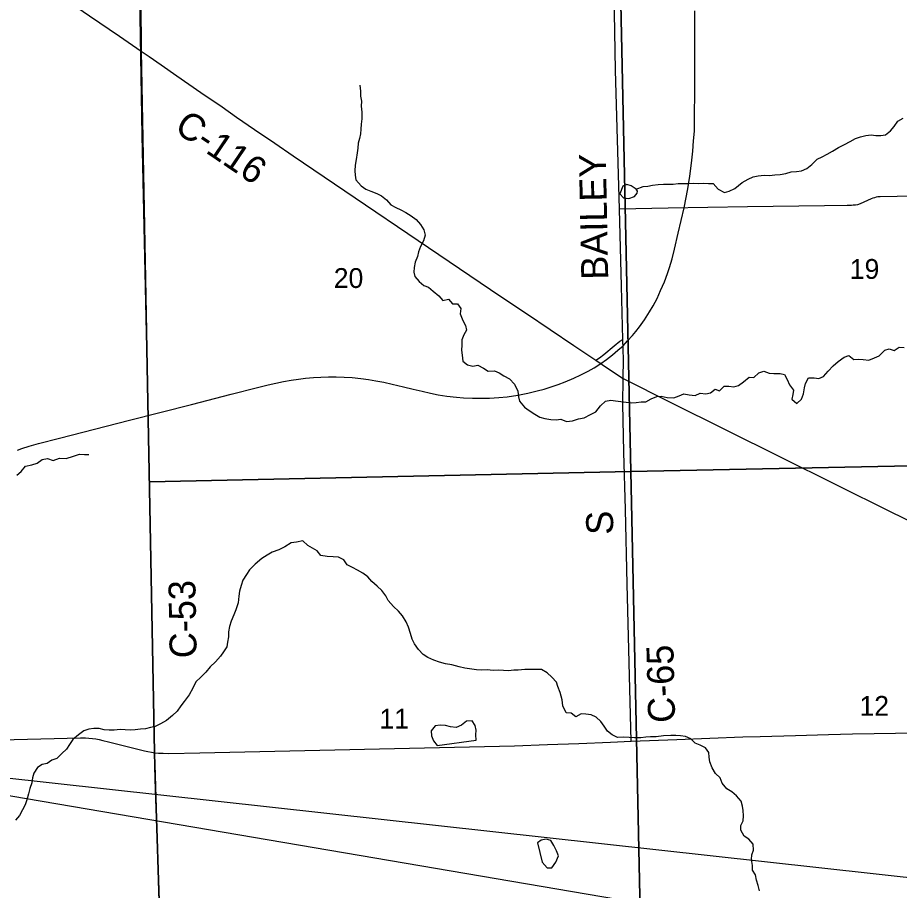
# Model space of a CAD drawing. Extents: x 0 to 34, y 0 to 22.
# Drawn here: x 6.483 to 8.341, y 13.008 to 14.847 of the extents above; entities that cross this region are included whole.
import ezdxf

# ---------------------------------------------------------------- set-up
doc = ezdxf.new("R2010")
doc.units = 0
for name, color, linetype in [('GM_X_Corporation', 7, 'Continuous'), ('GM_X_County_Road', 7, 'Continuous'), ('GM_X_County_Road_Text', 7, 'Continuous'), ('GM_X_Minor_Lake', 7, 'Continuous'), ('GM_X_Minor_River', 7, 'Continuous'), ('GM_X_Rail_Line', 7, 'Continuous'), ('GM_X_Section_Text', 7, 'Continuous'), ('GM_X_US_Route', 7, 'Continuous'), ('SH_Text', 7, 'Continuous')]:
    doc.layers.add(name, color=color, linetype=linetype)

msp = doc.modelspace()

# ---------------------------------------------------------------- linework, layer by layer
at = {"layer": 'GM_X_Corporation'}
for points in [[(9.5231, 10.8551), (9.5231, 15.9621), (9.2753, 15.9592), (8.467, 15.9428), (7.9287, 15.9357), (7.7194, 15.9329), (6.7217, 15.9197), (6.723, 15.8438), (6.7254, 15.7279), (6.7281, 15.6066), (6.7307, 15.471), (6.7334, 15.3315), (6.7355, 15.1761), (6.7389, 15.0216), (6.7431, 14.8113), (6.743, 14.7775), (6.7715, 13.2982), (6.7728, 13.2419), (6.7763, 13.1392), (6.7793, 13.0289), (6.7835, 12.8989)], [(6.7835, 12.8989), (6.7793, 13.0289), (6.7763, 13.1392), (6.7728, 13.2419), (6.7715, 13.2982), (6.743, 14.7775), (6.7431, 14.8113), (6.7389, 15.0216), (6.7355, 15.1761), (6.7334, 15.3315), (6.7307, 15.471), (6.7281, 15.6066), (6.7254, 15.7279), (6.723, 15.8438), (6.7217, 15.9197), (5.5749, 15.8972)]]:
    msp.add_lwpolyline(points, dxfattribs=at)
for points in [[(7.7535, 14.9111), (8.7607, 14.9294), (8.7817, 13.9109), (7.775, 13.8905)], [(6.74, 14.8913), (7.7535, 14.9111), (7.775, 13.8905), (6.7607, 13.8687), (6.7591, 13.9585), (6.7452, 14.5991)], [(8.7817, 13.9109), (8.8081, 12.8893), (7.797, 12.8624), (7.775, 13.8905)], [(7.775, 13.8905), (7.797, 12.8624), (6.7858, 12.8368), (6.7722, 13.2952), (6.7607, 13.8687)]]:
    msp.add_lwpolyline(points, close=True, dxfattribs=at)
at = {"layer": 'GM_X_County_Road'}
for points in [[(7.7586, 14.087), (7.7596, 14.1271), (7.7585, 14.1689), (7.7556, 14.2812), (7.7513, 14.4434), (7.7429, 14.7364), (7.7399, 14.8987), (7.7384, 14.9768), (7.7366, 15.1022), (7.7343, 15.2287), (7.732, 15.3689), (7.7302, 15.5067), (7.7285, 15.5987), (7.726, 15.729), (7.7231, 15.9143), (7.7228, 15.9196), (7.7225, 15.9234), (7.7219, 15.9266), (7.721, 15.9294), (7.7196, 15.9324), (7.7141, 15.942)], [(6.7432, 14.7769), (6.7433, 14.8108), (6.7391, 15.021), (6.7357, 15.1755), (6.7336, 15.331), (6.7309, 15.4704), (6.7283, 15.606), (6.7257, 15.7273), (6.7232, 15.8432), (6.7219, 15.9192)], [(5.583, 15.6276), (5.6406, 15.579), (5.6984, 15.53), (5.7316, 15.5018), (5.7952, 15.4488), (5.8729, 15.3853), (5.9476, 15.3251), (5.9861, 15.2948), (6.0143, 15.2742), (6.039, 15.257), (6.0726, 15.2344), (6.1308, 15.1946), (6.1902, 15.1544), (6.2678, 15.1015), (6.3063, 15.0753), (6.3366, 15.0543), (6.3799, 15.0246), (6.4366, 14.9859), (6.4904, 14.9497), (6.5207, 14.9291), (6.5698, 14.8958), (6.6343, 14.8515), (6.6973, 14.8086), (6.7432, 14.7769)], [(6.8063, 11.7845), (6.8015, 12.2917), (6.8011, 12.3125), (6.7964, 12.472), (6.7909, 12.6562), (6.7877, 12.7728), (6.7837, 12.8984), (6.7795, 13.0284), (6.7765, 13.1386), (6.773, 13.2414), (6.7717, 13.2976), (6.7432, 14.7769)], [(6.7432, 14.7769), (6.7599, 14.7656), (6.7855, 14.7476), (6.8182, 14.7248), (6.869, 14.6898), (6.9138, 14.6591), (6.9442, 14.6379), (6.982, 14.6119), (7.0246, 14.5827), (7.0631, 14.5562), (7.4572, 14.2892), (7.5013, 14.2598), (7.5553, 14.2236), (7.655, 14.1563), (7.7014, 14.1255), (7.7277, 14.1074), (7.7586, 14.087)], [(8.3758, 14.4713), (8.3366, 14.4705), (8.3003, 14.4699), (8.2959, 14.4695), (8.2918, 14.4687), (8.2884, 14.4678), (8.2847, 14.4665), (8.2816, 14.4651), (8.2584, 14.4548), (8.2525, 14.4529), (8.2484, 14.4522), (8.2437, 14.4519), (8.2399, 14.4516), (8.2358, 14.4516), (8.2312, 14.4516), (8.1834, 14.451), (8.0211, 14.4485), (7.8536, 14.4458), (7.7513, 14.4434)], [(7.7014, 14.1255), (7.7089, 14.1306), (7.718, 14.137), (7.7398, 14.1556), (7.752, 14.1654), (7.7585, 14.1689)], [(7.7757, 13.322), (7.7671, 13.653), (7.7639, 13.8108), (7.7602, 13.9313), (7.7582, 14.0333), (7.7586, 14.087)], [(7.7586, 14.087), (7.858, 14.037), (8.091, 13.921), (8.323, 13.8059), (8.4226, 13.7569), (8.6214, 13.6588), (8.8263, 13.5575), (8.9378, 13.5028), (9.0648, 13.4403), (9.1871, 13.3796)]]:
    msp.add_lwpolyline(points, dxfattribs=at)
at = {"layer": 'GM_X_Minor_Lake'}
for points in [[(7.7865, 14.4857), (7.7758, 14.4928), (7.7666, 14.4958), (7.7579, 14.4923), (7.752, 14.4763), (7.7593, 14.4672), (7.7707, 14.4662), (7.7825, 14.4705), (7.7885, 14.4777), (7.7888, 14.4815)], [(7.7888, 14.4815), (7.7865, 14.4857)], [(7.4491, 13.3245), (7.4486, 13.3355), (7.4489, 13.3454), (7.4473, 13.3552), (7.4408, 13.3654), (7.429, 13.3646), (7.4184, 13.3558), (7.4067, 13.3507), (7.3948, 13.3525), (7.3842, 13.3551), (7.3731, 13.3562), (7.3625, 13.3549), (7.3542, 13.3442), (7.3551, 13.3336), (7.3594, 13.3226), (7.3671, 13.3128)], [(7.4491, 13.3245), (7.4486, 13.3355), (7.4489, 13.3454), (7.4473, 13.3552), (7.4408, 13.3654), (7.429, 13.3646), (7.4184, 13.3558), (7.4067, 13.3507), (7.3948, 13.3525), (7.3842, 13.3551), (7.3731, 13.3562), (7.3625, 13.3549), (7.3542, 13.3442), (7.3551, 13.3336), (7.3594, 13.3226), (7.3671, 13.3128), (7.3667, 13.3139)], [(7.3671, 13.3128), (7.4491, 13.3245)], [(7.5879, 13.0675), (7.5987, 13.0554), (7.6089, 13.0555), (7.6168, 13.0669), (7.6224, 13.0807), (7.6185, 13.0909), (7.6131, 13.1023), (7.6065, 13.1132), (7.5966, 13.1154), (7.5864, 13.1138), (7.578, 13.1081)], [(7.578, 13.1081), (7.5879, 13.0675)]]:
    msp.add_lwpolyline(points, dxfattribs=at)
at = {"layer": 'GM_X_Minor_River'}
for points in [[(7.2038, 14.7049), (7.2054, 14.6924), (7.2055, 14.6818), (7.2071, 14.6715), (7.2064, 14.6609), (7.2081, 14.648), (7.2078, 14.6343), (7.2068, 14.6225), (7.2061, 14.6122), (7.2054, 14.6023), (7.2029, 14.5928), (7.2007, 14.5825), (7.1996, 14.5723), (7.1986, 14.5624), (7.196, 14.5483), (7.1939, 14.5361), (7.1936, 14.5247), (7.194, 14.5152), (7.1956, 14.5057), (7.2068, 14.4929), (7.2164, 14.4861), (7.2274, 14.4813), (7.2396, 14.4768), (7.2496, 14.4715), (7.2603, 14.4633), (7.2695, 14.4527), (7.2798, 14.4475), (7.2905, 14.4422), (7.3012, 14.4366), (7.3123, 14.4295), (7.3227, 14.4216), (7.3319, 14.411), (7.3388, 14.4004), (7.3416, 14.3887), (7.3383, 14.3768), (7.3319, 14.365), (7.3274, 14.3536), (7.3256, 14.3437), (7.3208, 14.3319), (7.3186, 14.3208), (7.3179, 14.3109), (7.3199, 14.3014), (7.3288, 14.2909), (7.3387, 14.2826), (7.3483, 14.2789), (7.3586, 14.271), (7.3705, 14.2612), (7.3789, 14.251), (7.3907, 14.2541), (7.3995, 14.2443), (7.4098, 14.2444), (7.4167, 14.2342), (7.4153, 14.2231), (7.4208, 14.2091), (7.4266, 14.1981), (7.4286, 14.1883), (7.4233, 14.1787), (7.4189, 14.1681), (7.4186, 14.157), (7.4183, 14.1464), (7.4195, 14.1358), (7.4212, 14.1232), (7.4307, 14.1157), (7.4418, 14.1124), (7.4524, 14.1147), (7.4643, 14.1087), (7.4742, 14.102), (7.4875, 14.1032), (7.4974, 14.0987), (7.5074, 14.092), (7.5192, 14.086), (7.5296, 14.0751), (7.5366, 14.0603), (7.5382, 14.0481), (7.5406, 14.0386), (7.5509, 14.0262), (7.5609, 14.019), (7.5724, 14.0115), (7.5835, 14.0055), (7.5941, 14.0022), (7.6063, 14.0004), (7.6174, 13.9994), (7.6276, 14.001), (7.6398, 13.9961), (7.652, 13.9977), (7.6649, 14.0016), (7.677, 14.004), (7.6903, 14.0106), (7.7013, 14.0167), (7.7114, 14.029), (7.7216, 14.0386), (7.733, 14.0409), (7.7429, 14.0395), (7.7539, 14.0381), (7.7654, 14.0366), (7.7764, 14.0356), (7.7863, 14.036), (7.7965, 14.0376), (7.8068, 14.0377), (7.8178, 14.0435), (7.8295, 14.0489)], [(7.7865, 14.4857), (7.8013, 14.4915), (7.8108, 14.4924), (7.821, 14.494), (7.8328, 14.4956), (7.8442, 14.4961), (7.8545, 14.4965), (7.8644, 14.4966), (7.875, 14.4974), (7.8963, 14.4976), (7.9073, 14.4981), (7.9169, 14.4978), (7.9286, 14.4986), (7.9385, 14.4979), (7.9484, 14.4976), (7.9588, 14.4859), (7.9726, 14.4785), (7.982, 14.4819), (7.9942, 14.4874), (8.0096, 14.5), (8.0221, 14.5066), (8.0327, 14.5116), (8.0434, 14.514), (8.0563, 14.5152), (8.0673, 14.5149), (8.0787, 14.5162), (8.0894, 14.517), (8.1019, 14.519), (8.1129, 14.5221), (8.1239, 14.523), (8.1349, 14.5246), (8.1459, 14.5296), (8.1565, 14.5377), (8.1678, 14.5488), (8.178, 14.5542), (8.1886, 14.5596), (8.2, 14.5662), (8.2125, 14.5739), (8.2253, 14.58), (8.2375, 14.5866), (8.2488, 14.5928), (8.2591, 14.5959), (8.2704, 14.5987), (8.2818, 14.6003), (8.2914, 14.5992), (8.302, 14.5989), (8.3115, 14.6001), (8.3225, 14.6086), (8.33, 14.6181), (8.3379, 14.6292), (8.3492, 14.6354)], [(7.8295, 14.0489), (7.839, 14.0498), (7.8516, 14.0464), (7.8657, 14.0462), (7.8771, 14.0505), (7.8869, 14.0543), (7.898, 14.0525), (7.9109, 14.0507), (7.9215, 14.0557), (7.9333, 14.0547), (7.9428, 14.0563), (7.9526, 14.064), (7.9622, 14.061), (7.972, 14.0706), (7.9819, 14.0707), (7.9921, 14.0692), (8.002, 14.072), (8.0126, 14.0797), (8.0247, 14.0893), (8.0342, 14.0886), (8.0447, 14.0985), (8.055, 14.1024), (8.0664, 14.0976), (8.0767, 14.0969), (8.0896, 14.0974), (8.0992, 14.0948), (8.1042, 14.0849), (8.1096, 14.0736), (8.1181, 14.0623), (8.1167, 14.0527), (8.1145, 14.0432), (8.1248, 14.0342), (8.135, 14.0434), (8.1391, 14.0544), (8.1413, 14.067), (8.1434, 14.0765), (8.1494, 14.0883), (8.1616, 14.0881), (8.1715, 14.0866), (8.1814, 14.0909), (8.1911, 14.102), (8.2017, 14.1131), (8.2119, 14.1227), (8.2247, 14.1319), (8.2346, 14.135), (8.2453, 14.1271), (8.2552, 14.1272), (8.2647, 14.1265), (8.2769, 14.1255), (8.2886, 14.1305), (8.2985, 14.1348), (8.3102, 14.1463), (8.3197, 14.1494), (8.3303, 14.1457), (8.3406, 14.1526), (8.3508, 14.1523)], [(6.5239, 13.9082), (6.5348, 13.916), (6.5454, 13.9182), (6.5573, 13.9139), (6.5708, 13.9188), (6.5849, 13.9183), (6.6004, 13.9233), (6.6132, 13.9274), (6.6235, 13.9268), (6.633, 13.9263)], [(6.4808, 13.8832), (6.4905, 13.891), (6.4993, 13.9019), (6.5126, 13.9045), (6.5239, 13.9082)], [(7.2851, 13.5965), (7.2751, 13.6063), (7.2636, 13.6191), (7.2585, 13.6289), (7.2505, 13.6395), (7.2405, 13.6493), (7.2294, 13.6587), (7.2205, 13.6689), (7.2102, 13.6764), (7.1991, 13.6824), (7.1888, 13.688), (7.177, 13.6937), (7.1704, 13.7046), (7.1589, 13.7099), (7.1475, 13.7109), (7.1353, 13.7116), (7.1216, 13.7137), (7.1143, 13.7236), (7.1044, 13.7292), (7.0941, 13.7348), (7.0837, 13.7446), (7.0704, 13.7418), (7.0594, 13.7402), (7.0458, 13.7318), (7.0333, 13.7256), (7.0189, 13.7205), (7.0083, 13.7144), (6.9973, 13.707), (6.9837, 13.6952), (6.9717, 13.6833), (6.9653, 13.6737), (6.9574, 13.6615), (6.9537, 13.6501), (6.9504, 13.6386), (6.9489, 13.628), (6.9472, 13.6135), (6.9423, 13.5994), (6.9383, 13.5884), (6.9327, 13.5754), (6.929, 13.5636), (6.9275, 13.5525), (6.9269, 13.5419), (6.9247, 13.5312), (6.9233, 13.5213), (6.9169, 13.5107), (6.9105, 13.5011), (6.8996, 13.4896), (6.8883, 13.4789), (6.8792, 13.4678), (6.8687, 13.4574), (6.8585, 13.4471), (6.8521, 13.4337), (6.8443, 13.4196), (6.8334, 13.4062), (6.827, 13.3967), (6.8187, 13.3852), (6.8089, 13.3764), (6.7968, 13.366), (6.7836, 13.3587), (6.7726, 13.3533), (6.7631, 13.3509), (6.7521, 13.3482), (6.7415, 13.3477), (6.7308, 13.3461), (6.7209, 13.3456), (6.7092, 13.3459), (6.6989, 13.3466), (6.686, 13.3454), (6.6757, 13.3453), (6.6654, 13.3463), (6.6547, 13.3489), (6.6433, 13.3488), (6.6331, 13.3472), (6.6221, 13.3441), (6.6111, 13.3353), (6.5994, 13.3257), (6.5919, 13.315), (6.5855, 13.3054), (6.5757, 13.2962), (6.5652, 13.2859), (6.5545, 13.282), (6.5447, 13.2754), (6.5348, 13.2731), (6.5246, 13.2669), (6.5171, 13.2551), (6.5142, 13.2448), (6.5124, 13.2341), (6.5083, 13.2223), (6.5057, 13.2109), (6.502, 13.1987), (6.4987, 13.188), (6.4927, 13.1773), (6.4867, 13.1659), (6.4781, 13.1555)], [(8.0464, 13.0065), (8.0436, 13.0179), (8.0401, 13.0289), (8.0381, 13.0403), (8.0315, 13.0505), (8.0311, 13.06), (8.0294, 13.0725), (8.0301, 13.0828), (8.0338, 13.0923), (8.0326, 13.1052), (8.0237, 13.1154), (8.0142, 13.1222), (8.0068, 13.1347), (8.0067, 13.1445), (8.0116, 13.1541), (8.0123, 13.1651), (8.0118, 13.1758), (8.0102, 13.1852), (8.0074, 13.1955), (7.9978, 13.2068), (7.9879, 13.2155), (7.9775, 13.2215), (7.9675, 13.2336), (7.9636, 13.2449), (7.9537, 13.2544), (7.9463, 13.2661), (7.9413, 13.2786), (7.9401, 13.2888), (7.9392, 13.2987), (7.9327, 13.3085), (7.9212, 13.3138), (7.9109, 13.3183), (7.9013, 13.3269), (7.8902, 13.3322), (7.8799, 13.3332), (7.8701, 13.3339), (7.8594, 13.3342), (7.8442, 13.3337), (7.8286, 13.3317), (7.8164, 13.3312), (7.8069, 13.3304), (7.7963, 13.3291), (7.783, 13.329), (7.7712, 13.3301), (7.7602, 13.3304), (7.7469, 13.3303), (7.7354, 13.3359), (7.7258, 13.3434), (7.7185, 13.3536), (7.7116, 13.3634), (7.702, 13.3728), (7.6913, 13.3777), (7.6802, 13.3795), (7.6707, 13.3798), (7.6594, 13.3733), (7.649, 13.3812), (7.6391, 13.3819), (7.6318, 13.397), (7.6302, 13.4095), (7.6262, 13.4251), (7.6215, 13.4372), (7.6184, 13.4467), (7.6088, 13.4569), (7.5988, 13.4663), (7.587, 13.4734), (7.5748, 13.4733), (7.563, 13.4736), (7.5516, 13.4731), (7.5379, 13.4719), (7.5284, 13.4718), (7.5174, 13.4702), (7.5064, 13.4709), (7.4961, 13.4719), (7.4847, 13.4715), (7.4725, 13.4725), (7.4596, 13.472), (7.4497, 13.4723), (7.4402, 13.4738), (7.4249, 13.4759), (7.4131, 13.4789), (7.3975, 13.4829), (7.3845, 13.4855), (7.372, 13.4888), (7.3601, 13.4933), (7.3472, 13.4985), (7.3376, 13.5049), (7.3276, 13.5154), (7.3191, 13.5275), (7.3141, 13.5374), (7.3106, 13.5495), (7.3067, 13.5624), (7.3016, 13.5738), (7.2935, 13.5866), (7.2851, 13.5965)]]:
    msp.add_lwpolyline(points, dxfattribs=at)
at = {"layer": 'GM_X_Rail_Line'}
msp.add_lwpolyline([(6.4823, 13.9357), (6.4918, 13.9391), (6.5072, 13.9438), (6.5269, 13.9495), (6.5711, 13.9606), (6.7182, 13.9986), (6.8489, 14.0322), (6.9331, 14.0537), (6.9884, 14.0676), (7.011, 14.0736), (7.0269, 14.0772), (7.0433, 14.0804), (7.0594, 14.0834), (7.0745, 14.0856), (7.0893, 14.0874), (7.1062, 14.0889), (7.122, 14.0898), (7.1379, 14.0903), (7.1538, 14.0902), (7.1709, 14.0898), (7.1879, 14.0887), (7.2062, 14.0868), (7.222, 14.0847), (7.2379, 14.082), (7.2544, 14.0789), (7.2719, 14.0751), (7.2963, 14.0693), (7.3165, 14.0642), (7.3353, 14.0597), (7.3527, 14.0557), (7.369, 14.0526), (7.3872, 14.0496), (7.4073, 14.0474), (7.4223, 14.046), (7.4411, 14.045), (7.4579, 14.0449), (7.477, 14.0452), (7.497, 14.0467), (7.5145, 14.0484), (7.5368, 14.0515), (7.5581, 14.0558), (7.5774, 14.0604), (7.5921, 14.0645), (7.6071, 14.069), (7.622, 14.0741), (7.6365, 14.0797), (7.6551, 14.0876), (7.67, 14.0947), (7.6848, 14.1024), (7.6977, 14.1095), (7.7118, 14.1181), (7.7238, 14.127), (7.7367, 14.1366), (7.7479, 14.1462), (7.7586, 14.1558), (7.7682, 14.1658), (7.7784, 14.1771), (7.7858, 14.1859), (7.7932, 14.1955), (7.8036, 14.2101), (7.8147, 14.2275), (7.822, 14.2398), (7.8303, 14.2554), (7.8379, 14.2724), (7.8461, 14.2905), (7.8526, 14.3083), (7.8567, 14.3206), (7.862, 14.3389), (7.8671, 14.3596), (7.875, 14.3928), (7.8873, 14.4463), (7.8952, 14.4866), (7.8993, 14.513), (7.903, 14.5409), (7.9056, 14.5661), (7.9074, 14.5877), (7.9089, 14.608), (7.9095, 14.6252), (7.9102, 14.7061), (7.9098, 14.8616)], dxfattribs=at)
at = {"layer": 'GM_X_US_Route'}
for points in [[(6.7717, 13.2976), (6.7794, 13.2972), (6.7892, 13.2966), (6.8011, 13.2964), (6.8666, 13.2974), (7.5298, 13.3126), (7.5994, 13.3152), (7.6652, 13.3176), (7.732, 13.3202), (7.7757, 13.322), (7.8718, 13.326), (8.0114, 13.3313), (8.0476, 13.3324), (8.1219, 13.3345), (8.1919, 13.336), (8.2421, 13.3375), (8.3788, 13.3401), (8.5594, 13.3434), (8.7239, 13.3465), (8.8928, 13.3501), (9.0056, 13.3526)], [(4.9824, 13.2942), (5.1685, 13.2962), (5.4013, 13.3001), (5.7198, 13.3065), (5.9449, 13.3125), (6.6155, 13.3293), (6.6257, 13.3291), (6.633, 13.3287), (6.6406, 13.3278), (6.6475, 13.3269), (6.6544, 13.3255), (6.662, 13.3239), (6.6744, 13.321), (6.7079, 13.3126), (6.7499, 13.302), (6.7717, 13.2976)]]:
    msp.add_lwpolyline(points, dxfattribs=at)
at = {"layer": 'SH_Text'}
msp.add_lwpolyline([(10.1431, 12.8377), (5.8618, 13.3103), (10.1431, 12.581)], close=True, dxfattribs=at)

# ---------------------------------------------------------------- texts
at = {"layer": 'GM_X_County_Road_Text'}
for s, height, rotation, p in [('C-116', 0.05682, 325.9294, (6.8104, 14.609)), ('BAILEY', 0.05682, 91.1161, (7.7275, 14.2954)), ('S', 0.0568, 91.2448, (7.7383, 13.7578)), ('C-53', 0.05682, 91.0286, (6.8602, 13.4975)), ('C-65', 0.05682, 91.3713, (7.8685, 13.3615))]:
    msp.add_text(s, height=height, rotation=rotation, dxfattribs=at).set_placement(p)
at = {"layer": 'GM_X_Section_Text'}
for s, p in [('19', (8.2365, 14.2967)), ('20', (7.149, 14.2775)), ('12', (8.2569, 13.3757)), ('11', (7.2453, 13.3487))]:
    msp.add_text(s, height=0.04186, rotation=0, dxfattribs=at).set_placement(p)

doc.saveas('drawing.dxf')
